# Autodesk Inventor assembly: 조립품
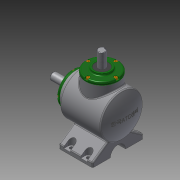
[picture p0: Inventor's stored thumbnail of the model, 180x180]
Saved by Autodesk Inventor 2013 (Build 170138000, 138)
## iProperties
Created: 2017-04
Part Number: 조립품
Document SubType Name: Assembly
Designer: Administrator
Author: Administrator
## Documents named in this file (14)
- C:\Users\Administrator\Desktop\470408V1007\조립품.iam
- C:\Users\Administrator\Desktop\470408V1007\1. 본체.ipt
- C:\Users\Administrator\Desktop\470408V1007\메인 축.ipt
- 메인 축.ipt
- C:\Users\Administrator\Desktop\470408V1007\커버.ipt
- C:\Users\Administrator\Desktop\470408V1007\베어링 6203.ipt
- C:\Users\Administrator\Desktop\470408V1007\오일실 17 32 8.ipt
- C:\Users\Administrator\Desktop\470408V1007\키 5x5.ipt
- C:\Users\Administrator\Desktop\470408V1007\메인 베벨기어.ipt
- C:\Users\Administrator\Desktop\470408V1007\서브 베벨기어.ipt
- C:\Users\Administrator\Desktop\470408V1007\서브 축.ipt
- 서브 축.ipt
- C:\Users\Administrator\Desktop\470408V1007\키 4x4.ipt
- C:\Users\Administrator\Desktop\470408V1007\볼트 M4.ipt
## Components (1 placed, 1 different names)
1. 1. 본체:1
